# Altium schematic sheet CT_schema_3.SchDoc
size 298 x 159 mm
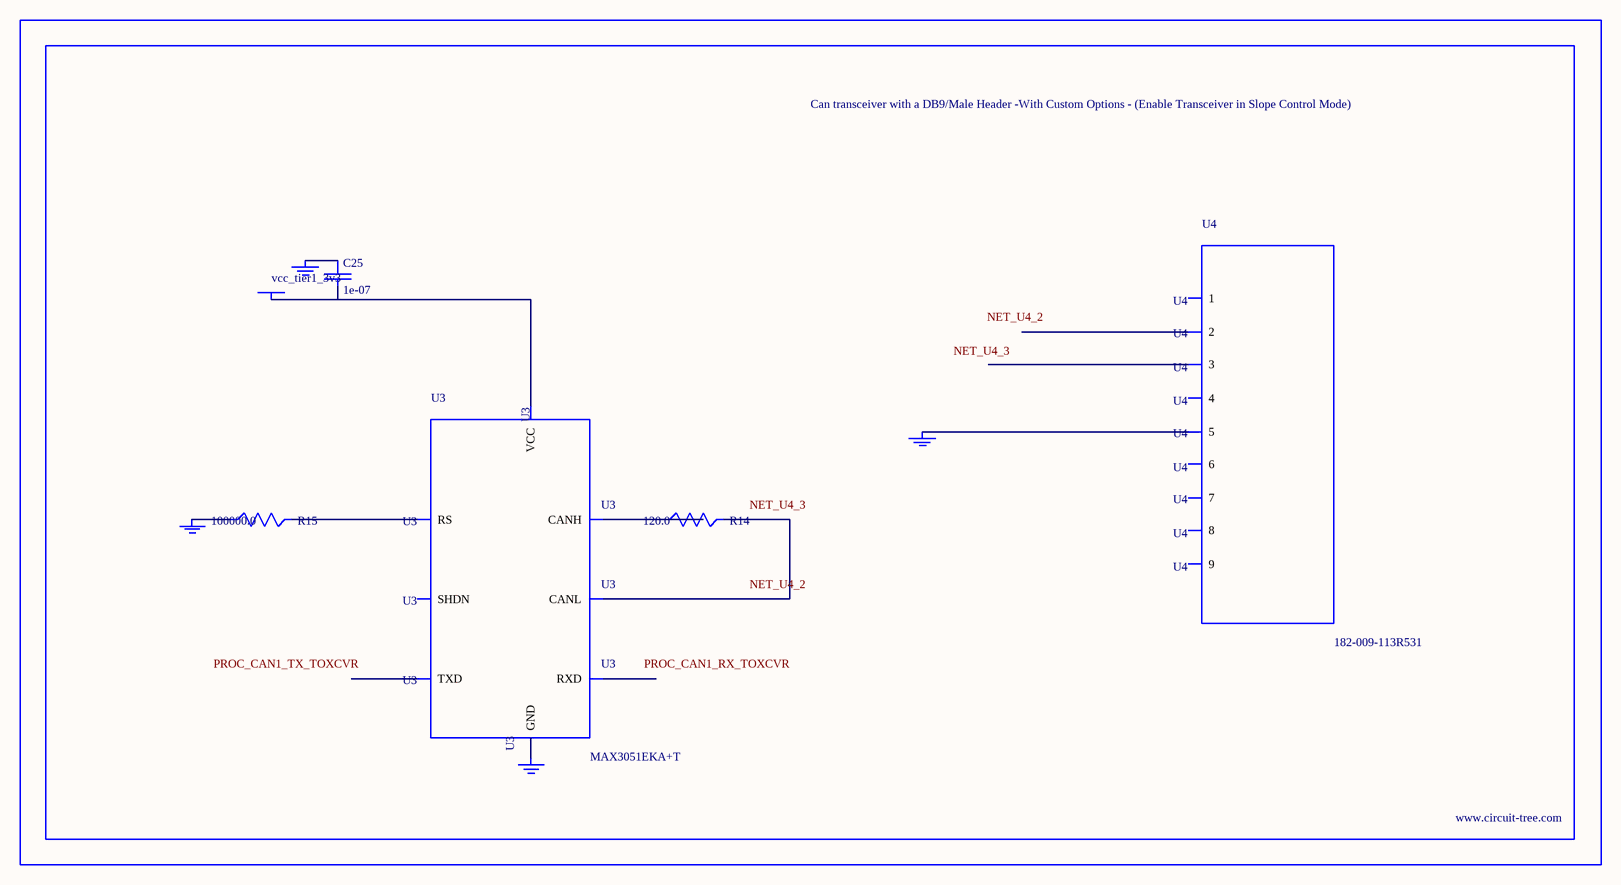
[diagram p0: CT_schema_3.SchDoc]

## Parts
BORDER2  (no value)
C25  1e-07  [C0402]
GND_INSTANCE_2_0  (no value)
GND_INSTANCE_2_1  (no value)
GND_INSTANCE_2_2  (no value)
GND_INSTANCE_2_3  (no value)
POWER_INSTANCE_2_0  vcc_tier1_3v3
R14  120.0  [R0603]
R15  100000.0  [R0603]
U3  MAX3051EKA+T  [SOT-23-8]
U4  182-009-113R531  [182-009-MALE]

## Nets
NetC25_1: C25.1 GND_INSTANCE_2_0.0(GND)
NetC25_2: C25.2 POWER_INSTANCE_2_0.0(PWR) U3.3(VCC)
NetGND_INSTANCE_2_1_0: GND_INSTANCE_2_1.0(GND) R15.1
NetGND_INSTANCE_2_2_0: GND_INSTANCE_2_2.0(GND) U3.2(GND)
NetGND_INSTANCE_2_3_0: GND_INSTANCE_2_3.0(GND) U4.5
NetR14_1: R14.1 U3.7(CANH)
NetR14_2: R14.2 U3.6(CANL)
NetR15_2: R15.2 U3.8(RS)

Not connected (* = marked no-connect by the designer): U3 1(TXD) 4(RXD) 5(SHDN); U4 1 2 3 4 6 7 8 9

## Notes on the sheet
- Labels drawn without touching a wire or pin: NET_U4_2, NET_U4_3, PROC_CAN1_RX_TOXCVR, PROC_CAN1_TX_TOXCVR

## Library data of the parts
BORDER2 = BORDER_PAGE2
C25 = C0402C104K3RACTU
GND_INSTANCE_2_0-GND_INSTANCE_2_3 = GND
POWER_INSTANCE_2_0 = PWR
R14 = RC0603JR-07120RL
R15 = RC0603JR-07100KL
